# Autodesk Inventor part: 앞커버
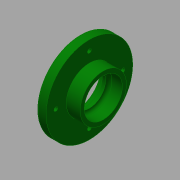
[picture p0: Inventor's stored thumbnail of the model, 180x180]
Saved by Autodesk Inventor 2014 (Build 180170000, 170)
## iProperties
Created: 2015-09
Part Number: 앞커버
Material: 알루미늄 6061
Document SubType Name: Modeling
Designer: mduedu
Density: 2.71 g/cm^3
Mass: 58.9874 g
Surface Area: 98.7754 cm^2
Volume: 21.7666 cm^3
Appearance: 진녹색
Author: mduedu
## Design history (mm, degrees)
sketch "스케치1"
  geometry: L1 (-4, 67)-(-16, 67); L2 (-16, 67)-(-16, 84.5); L3 (-16, 84.5)-(-24, 84.5); L4 (-24, 84.5)-(-24, 70.5); L5 (-27, 70.5)-(-27, 61); L6 (-27, 61)-(-4, 61); L7 (-4, 61)-(-4, 67); L8 (-79.5, 39.5)-(-79.5, 54.5) reference; L9 (48.5, 54.5)-(48.5, 39.5) reference; L10 (-79.5, 47)-(48.5, 47); L11 (-24, 70.5)-(-27, 70.5); 3 further points
  constraints: 18 end point, 6 parallel, 4 midpoint, 1 horizontal, 1 perpendicular, 1 vertical alignment
  dimensions: "d0" = 23 distance between parallel lines of L7 L5; "d2" = 28 diameter of L6 L10; "d3" = 40 diameter of L1 L10; "d5" = 12 distance of L1.start L1.end; "d6" = 75 diameter of L3 L10; "d7" = 8 distance of L2.end L3.end; "d8" = 47 diameter of L4.end L10
revolve "회전1" sketch "스케치1" stored, may be unused: angle "d4" = 90 deg
sketch "스케치2"
  geometry: C1 r 37.5 at (0, 0) reference; 2 further points
  constraints: 1 coincident
hole "구멍1" sketch "스케치2" at (0, 0) diameter "d11" = 33; stored, may be unused: countersink angle "d15" = 90 deg, drill point angle "d17" = 0 deg; dims "d12" = 6, "d13" = 4, "d14" = 2, "d16" = 12
fillet "모깎기1" dims "d18" = 3
fillet "모깎기2" dims "d19" = 1
sketch "스케치3"
  geometry: C1 r 37.5 at (0, 0) reference; 2 further points
  constraints: 1 coincident
hole "구멍2" sketch "스케치3" at (0, 0) diameter "d20" = 40; stored, may be unused: countersink angle "d24" = 90 deg, drill point angle "d26" = 0 deg; dims "d21" = 6, "d22" = 4, "d23" = 2, "d25" = 8
fillet "모깎기3" dims "d27" = 0.4
chamfer "모따기1" distance "d28" = 1; stored, may be unused: second distance "d29" = 2, angle "d30" = 30 deg
sketch "스케치7" dims "d56" = 58
  geometry: C1 r 37.5 at (0, 0) reference; 5 further points
  constraints: 2 vertical alignment, 1 coincident, 7 other
  dimensions: "d59" = 360 deg dimension on C1.centre point (0, 29) (derived)
hole "구멍4" sketch "스케치7" at (0, 29), (-29, 0), (0, -29), (29, 0) diameter "d48" = 3.4; stored, may be unused: countersink angle "d52" = 90 deg, drill point angle "d54" = 0 deg; dims "d49" = 6, "d50" = 6.5, "d51" = 3.4, "d53" = 8
node "솔리드1"
node "참조1"
node "참조2"
